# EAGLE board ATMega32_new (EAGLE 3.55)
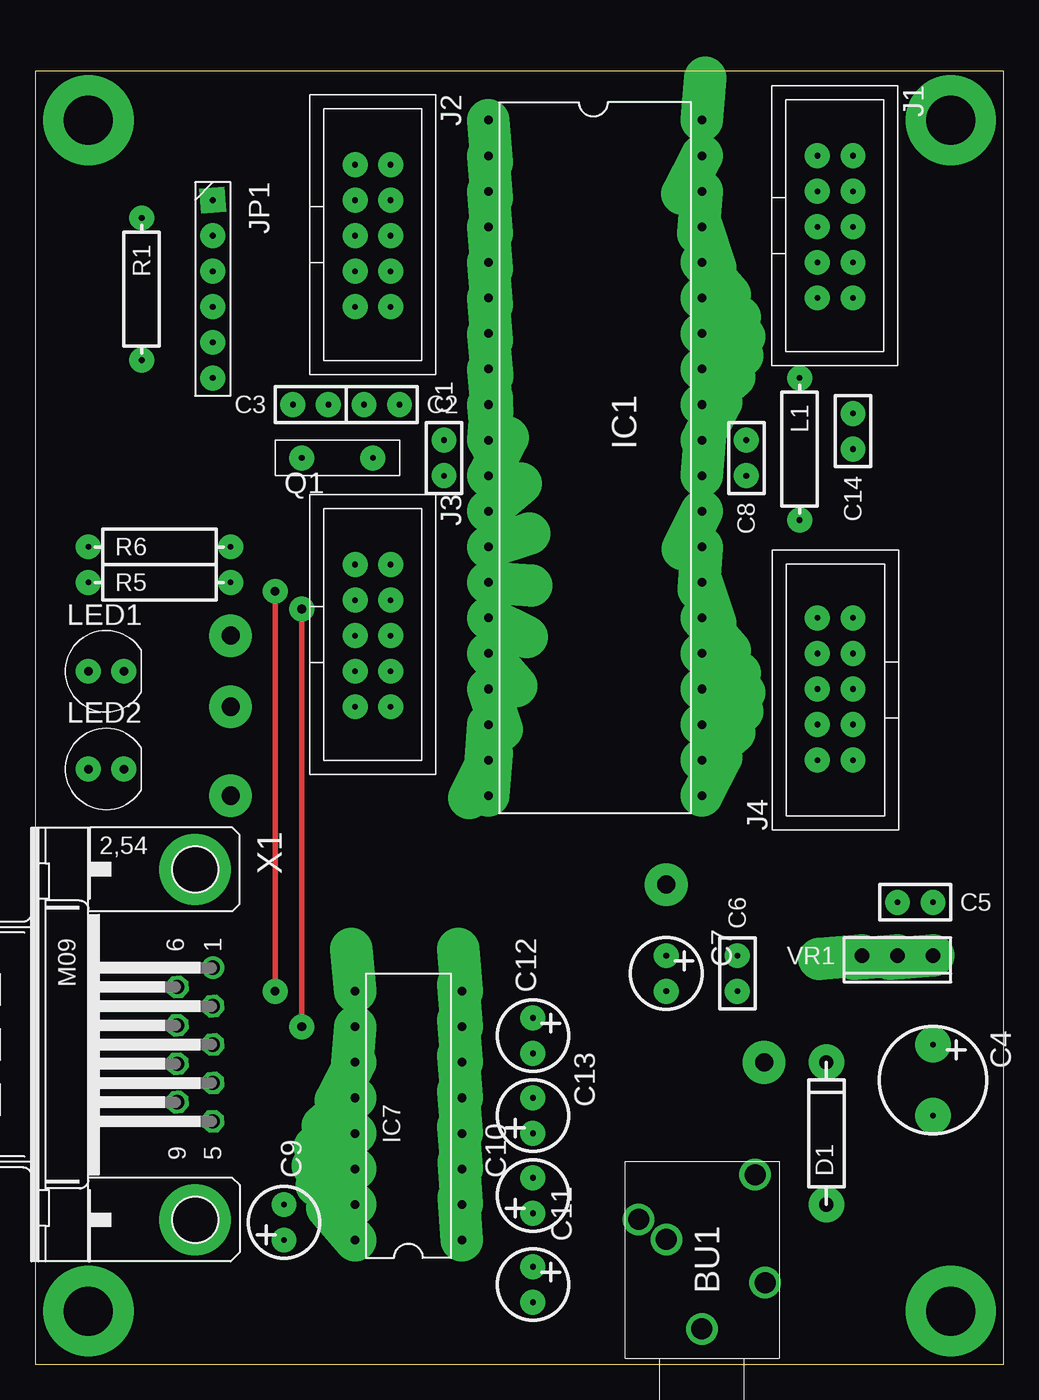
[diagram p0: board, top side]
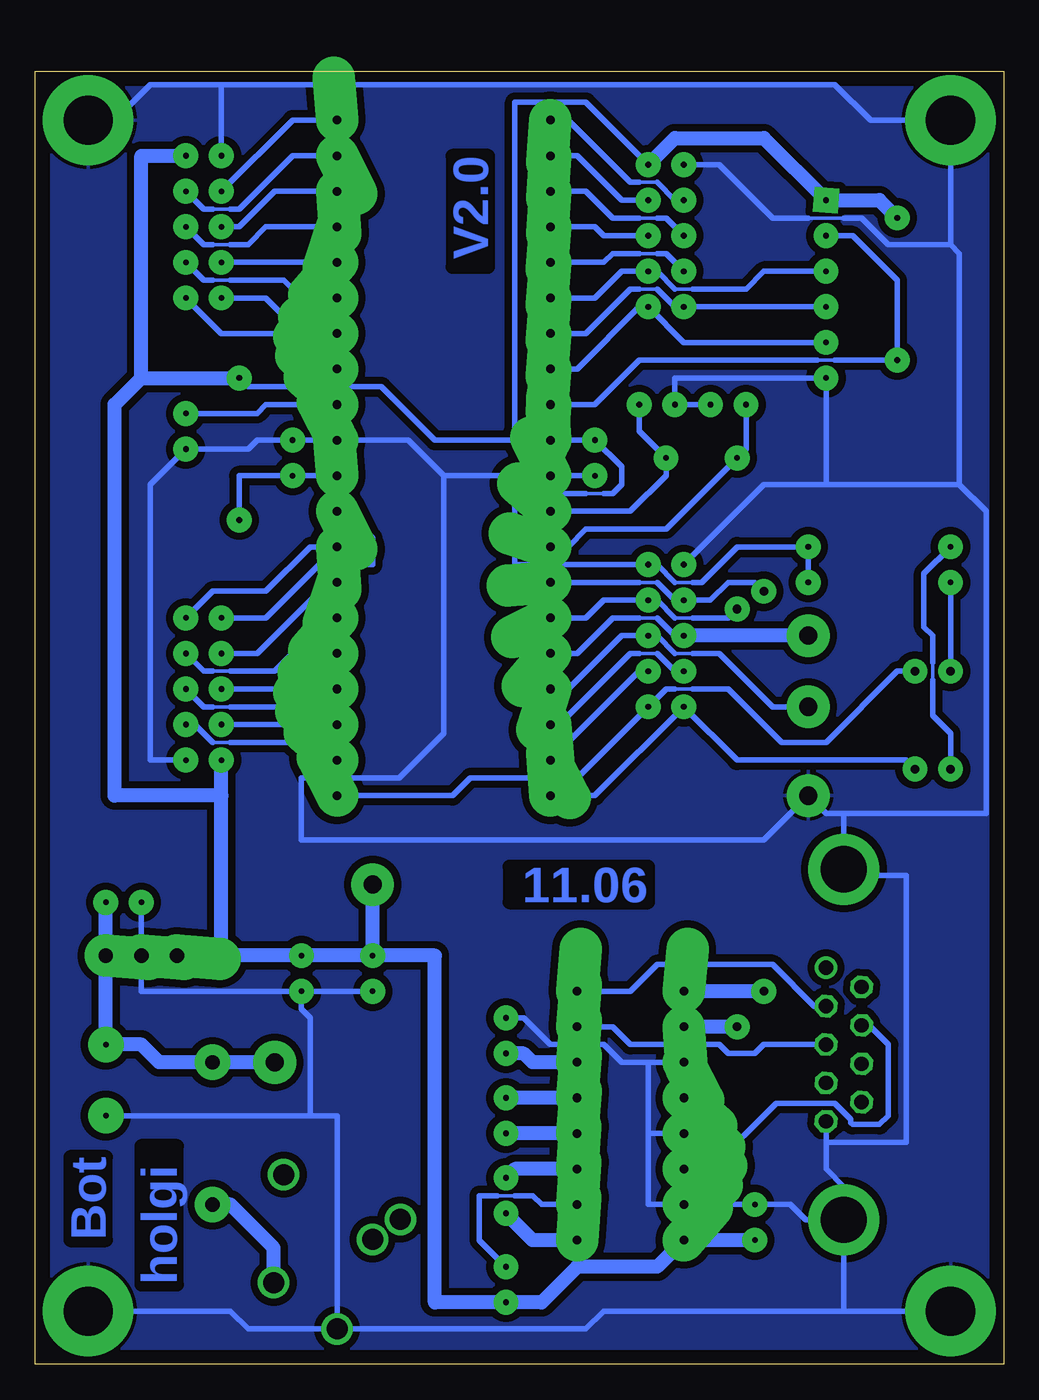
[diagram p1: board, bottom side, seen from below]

Size 69.19 x 92.38 mm. Coordinates in mm from the lower left corner, seen from the top.
Outline: 0,0 69.19,0 69.19,92.38 0,92.38 0,0
Copper layers used: Top, Bottom

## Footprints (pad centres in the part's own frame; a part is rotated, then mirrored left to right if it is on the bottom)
_3,5MM = drill 1.499 pad 2.184 round:  0,0;  3.302,-4.521;  7.823,4.521;  6.401,2.54;  11.024,-3.81
RM2,5 = drill 0.406 pad 1.778 round:  -1.27,0;  1.27,0
KO02 = drill 0.406 pad 2.54 round:  -2.54,0;  2.54,0
KO01 = drill 0.406 pad 1.778 round:  -1.27,0;  1.27,0
O_1A = drill 1.016 pad 2.54 round:  -5.08,0;  5.08,0
L-40B = drill 0.61 pad 3.048 offset:  -24.13,-7.62;  -21.59,-7.62;  -8.89,-7.62;  -6.35,-7.62;  -19.05,-7.62;  -16.51,-7.62;  -11.43,-7.62;  -13.97,-7.62;  -3.81,-7.62;  -1.27,-7.62;  1.27,-7.62;  3.81,-7.62;  6.35,-7.62;  8.89,-7.62;  11.43,-7.62;  13.97,-7.62;  16.51,-7.62;  19.05,-7.62;  21.59,-7.62;  24.13,-7.62;  24.13,7.62;  21.59,7.62;  19.05,7.62;  16.51,7.62;  13.97,7.62;  11.43,7.62;  8.89,7.62;  6.35,7.62;  3.81,7.62;  1.27,7.62;  -1.27,7.62;  -3.81,7.62;  -6.35,7.62;  -8.89,7.62;  -11.43,7.62;  -13.97,7.62;  -16.51,7.62;  -19.05,7.62;  -21.59,7.62;  -24.13,7.62
L-16B = drill 0.61 pad 3.048 offset:  -8.89,-3.81;  -6.35,-3.81;  6.35,-3.81;  8.89,-3.81;  -3.81,-3.81;  -1.27,-3.81;  3.81,-3.81;  1.27,-3.81;  8.89,3.81;  6.35,3.81;  3.81,3.81;  1.27,3.81;  -1.27,3.81;  -3.81,3.81;  -6.35,3.81;  -8.89,3.81
5 = drill 0.406 pad 1.778 round:  0,0;  2.54,0;  5.08,0;  7.62,0;  10.16,0;  10.16,2.54;  7.62,2.54;  5.08,2.54;  2.54,2.54;  0,2.54
6 = drill 0.406 pad 1.778 square:  0,0 | drill 0.406 pad 1.778 round:  5.08,0;  10.16,0;  12.7,0;  7.62,0;  2.54,0
S04 = drill 0.406 pad 1.778 round:  -5.08,0;  5.08,0
D_5MM = drill 0.61 pad 1.778 round:  -1.27,0;  1.27,0
GEL = drill 1.295 pad 3.048 round:  0,0
ARZ_ST = drill 0.406 pad 1.778 round:  -2.54,0;  2.54,0
HRUNG = drill 3.505 pad 6.452 round:  0,0
220A = drill 1.016 pad 3.048 offset:  -2.54,0;  0,0;  2.54,0
9HP = drill 1.016 pad 1.6 octagon:  5.486,1.27;  2.743,1.27;  0,1.27;  -2.743,1.27;  4.115,-1.27;  1.372,-1.27;  -1.372,-1.27;  -4.115,-1.27 | drill 1.016 pad 1.6 round:  -5.486,1.27 | drill 3.302 pad 5.08 round:  -12.522,0;  12.522,0

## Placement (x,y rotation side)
BU1  BU_3,5MM  [_3,5MM]  47.62,2.54 90 top
C1  C100NK  [RM2,5]  29.21,64.77 90 top
C2  22p  [RM2,5]  24.77,68.58 0 top
C3  22p  [RM2,5]  19.68,68.58 180 top
C4  470u/25  [KO02]  64.14,20.32 270 top
C5  C100NK  [RM2,5]  62.87,33.02 0 top
C6  C100NK  [RM2,5]  50.16,27.94 90 top
C7  100u  [KO01]  45.09,27.94 270 top
C8  C100NK  [RM2,5]  50.8,64.77 270 top
C9  10u  [KO01]  17.78,10.16 90 top
C10  10u  [KO01]  35.56,12.06 90 top
C11  10u  [KO01]  35.56,5.71 270 top
C12  10u  [KO01]  35.56,23.5 270 top
C13  10u  [KO01]  35.56,17.78 90 top
C14  C100NK  [RM2,5]  58.42,66.67 270 top
D1  1N4001  [O_1A]  56.52,16.51 90 top
IC1  90S8535-P  [L-40B]  40.01,64.77 270 top
IC7  MAX232  [L-16B]  26.67,17.78 90 top
J1  8BITPORT  [5]  55.88,86.36 270 top
J2  8BITPORT  [5]  22.86,85.72 270 top
J3  8BITPORT  [5]  22.86,57.15 270 top
J4  8BITPORT  [5]  58.42,43.18 90 top
JP1  PINHD-1X6  [6]  12.7,83.19 270 top
L1  100uH  [S04]  54.61,65.41 270 top
LED1  rot  [D_5MM]  5.08,49.53 0 top
LED2  grn  [D_5MM]  5.08,42.55 0 top
N1  Int1  [GEL]  13.97,46.99 0 top
N2  Int0  [GEL]  13.97,52.07 0 top
N3  gnd  [GEL]  13.97,40.64 0 top
N4  +5V  [GEL]  45.09,34.29 0 top
N5  +Ub  [GEL]  52.07,21.59 0 top
Q1  8MHz  [ARZ_ST]  21.59,64.77 0 top
R1  100k  [S04]  7.62,76.83 270 top
R5  1k  [S04]  8.89,55.88 0 top
R6  1k  [S04]  8.89,58.42 0 top
U$30  BOHRUNG  [HRUNG]  3.81,88.9 0 top
U$31  BOHRUNG  [HRUNG]  65.41,88.9 0 top
U$32  BOHRUNG  [HRUNG]  65.41,3.81 0 top
U$33  BOHRUNG  [HRUNG]  3.81,3.81 0 top
VR1  7805  [220A]  61.59,29.21 180 top
X1  M09HP  [9HP]  11.43,22.86 270 top

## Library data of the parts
BU1 = bts
C1-C14 D1 IC1 IC7 J1-J4 JP1 L1 LED1 LED2 Q1 R1 R5 R6 VR1 = holg_plt
N1-N5 U$30-U$33 = holgnorm
X1 = subd-a

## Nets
+5V: C1. C6. C7. C9. C11. IC1. IC7. J1. J2. J3. J4. JP1. L1. N4. R1. R5. R6. VR1.
GND: BU1. C1. C2. C3. C4. C5. C6. C7. C8. C9. C12. C14. IC1. IC7. J1. J2. J3. J4. JP1. N3. U$30. U$31. U$32. U$33. VR1. X1.
INT0: IC1. J3. N2.
INT1: IC1. J3. N1.
LCD_CS: IC1. J3.
LCD_RS: IC1. J3.
MISO: IC1. J2. JP1.
MOSI: IC1. J2. JP1.
N$1: IC1. J4.
N$2: IC1. J4.
N$3: IC1. J4.
N$4: IC1. J4.
N$5: IC1. J4.
N$6: C3. IC1. Q1.
N$7: IC1. J4.
N$8: C2. IC1. Q1.
N$9: C12. IC7.
N$10: C11. IC7.
N$11: IC1. J4.
N$12: C10. IC7.
N$13: C13. IC7.
N$14: IC1. J1.
N$15: C10. IC7.
N$16: IC1. J4.
N$17: C13. IC7.
N$18: IC1. J1.
N$19: IC1. J1.
N$21: IC1. J1.
N$22: IC1. J1.
N$23: IC1. J1.
N$24: C8. IC1. L1.
N$25: IC1. J1.
N$26: IC1. J1.
N$27: C14. IC1.
N$29: IC1. J3. LED1.
N$30: IC1. J2.
N$31: IC1. J2.
N$32: IC1. J2.
N$33: IC1. J2.
N$34: IC1. J2.
N$35: IC1. J3. LED2.
N$36: LED1. R5.
N$37: LED2. R6.
N$42: C4. C5. D1. N5. VR1.
N$50: BU1. D1.
RESET: IC1. JP1. R1.
RTS_OUT: IC7. X1.
RXD: IC1. IC7. J3.
RXD_IN: IC7. X1.
SCK: IC1. J2. JP1.
TXD: IC1. IC7. J3.
TXD_OUT: IC7. X1.

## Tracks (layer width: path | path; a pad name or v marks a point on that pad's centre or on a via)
+5V
  Bottom 0.254: 23.5,55.88 22.23,55.88 | 28.57,62.23 29.84,62.23
  Bottom 0.406: 34.92,66.04 32.38,66.04 C1. 27.3,64.14 27.3,62.87 27.94,62.23 28.57,62.23 | 54.61,70.48 53.98,69.85 44.45,69.85 40.64,66.04 34.92,66.04 | R5. R6. 19.05,58.42 21.59,55.88 22.23,55.88 | 23.5,55.88 24.77,57.15 J3. 34.92,57.15 34.92,62.23 29.84,62.23 | J2. 29.84,90.17 34.92,90.17 34.92,66.04
  Bottom 1.016: 17.78,8.89 IC7. 24.77,6.99 30.48,6.99 33.02,4.45 C11. 40.64,4.45 40.64,29.21 45.09,29.21 | 55.88,29.21 C6. 45.09,29.21 | 55.88,29.21 VR1. | 7.62,81.92 8.89,83.19 12.7,83.19 17.14,87.63 23.5,87.63 J2. | 55.88,40.64 63.5,40.64 63.5,68.58 61.59,70.48 | 45.09,29.21 N4. | J1. 61.59,86.36 61.59,70.48 | 61.59,70.48 54.61,70.48 | 55.88,40.64 J4. | 55.88,29.21 55.88,40.64
GND
  Bottom 0.254: 11.43,81.92 13.97,81.92
  Bottom 0.406: X1. 11.43,12.7 12.7,13.97 12.7,15.88 | 12.7,15.88 12.7,17.37 | 12.7,15.88 6.99,15.88 6.99,34.92 8.89,34.92 9.35,35.38 11.43,35.38 11.43,39.37 | X1. 14.15,10.34 15.24,11.43 C9. 22.86,11.43 25.4,11.43 25.4,16.51 | 25.4,16.51 22.86,16.51 | 25.4,16.51 25.4,21.59 | 25.4,21.59 22.86,21.59 | 25.4,21.59 27.3,21.59 28.57,22.86 32.38,22.86 34.29,24.77 35.56,24.77 | 11.43,3.81 X1. | U$33. 11.43,3.81 | 47.62,2.54 29.84,2.54 28.57,3.81 11.43,3.81 | 61.59,33.02 61.59,29.21 61.59,26.67 50.16,26.67 | 50.16,26.67 C7. | U$32. 55.24,3.81 53.98,2.54 47.62,2.54 | 49.53,17.78 47.62,17.78 47.62,2.54 | 49.53,17.78 C4. | 49.53,17.78 49.53,24.77 50.16,25.4 50.16,26.67 | 22.86,85.72 20.32,85.72 16.51,81.92 13.97,81.92 | 3.17,62.87 1.27,60.96 1.27,39.37 11.43,39.37 | 55.88,91.44 12.06,91.44 9.53,88.9 U$30. 3.81,80.01 | 55.88,91.44 60.96,91.44 63.5,88.9 U$31. | 11.43,81.92 10.16,81.92 8.26,80.01 3.81,80.01 | 40.01,63.5 32.38,63.5 29.21,63.5 | 55.88,91.44 55.88,86.36 | 11.43,39.37 12.7,39.37 N3. 17.14,37.47 50.16,37.47 50.16,41.91 43.18,41.91 40.01,45.09 40.01,63.5 | 3.81,80.01 3.17,79.38 3.17,62.87 | 3.17,62.87 12.7,62.87 | 20.95,68.58 23.5,68.58 23.5,70.48 12.7,70.48 12.7,62.87 | 22.86,57.15 17.14,62.87 12.7,62.87 | 58.42,43.18 60.96,43.18 60.96,62.87 C14. 53.98,65.41 53.34,66.04 50.8,66.04 47.62,66.04 42.55,66.04 40.01,63.5
  pour Bottom (isolate 0.508): 0.64,91.44 0.64,0.64 68.58,0.64 68.58,91.44
INT0
  Bottom 0.254: 24.77,53.34 26.04,53.34
  Bottom 0.406: 22.86,52.07 23.5,52.07 24.77,53.34 | 32.38,50.8 30.48,50.8 27.94,53.34 26.04,53.34
  Bottom 1.016: N2. 22.86,52.07
INT1
  Bottom 0.254: 22.23,50.8 23.5,50.8
  Bottom 0.406: 23.5,50.8 24.77,52.07 25.4,52.07 27.3,52.07 31.11,48.26 32.38,48.26 | N1. 16.51,46.99 20.32,50.8 22.23,50.8
LCD_CS
  Bottom 0.254: 24.77,50.8 26.04,50.8
  Bottom 0.406: 22.86,49.53 23.5,49.53 24.77,50.8 | 32.38,45.72 31.75,45.72 26.67,50.8 26.04,50.8
LCD_RS
  Bottom 0.406: 25.4,49.53 26.04,49.53 32.38,43.18
MISO
  Bottom 0.254: 24.77,76.83 26.04,76.83
  Bottom 0.406: 12.7,75.56 22.86,75.56 23.5,75.56 24.77,76.83 | 32.38,73.66 29.84,73.66 26.67,76.83 26.04,76.83
MOSI
  Bottom 0.254: 22.23,76.83 23.5,76.83
  Bottom 0.406: 23.5,76.83 24.77,78.11 25.4,78.11 27.3,78.11 29.21,76.2 32.38,76.2 | 12.7,78.11 17.14,78.11 18.41,76.83 22.23,76.83
N$1
  Bottom 0.254: 55.24,44.45 56.52,44.45
  Bottom 0.406: 47.62,43.18 49.53,43.18 50.8,44.45 55.24,44.45 | 56.52,44.45 57.78,45.72 58.42,45.72
N$2
  Bottom 0.406: 47.62,45.72 55.88,45.72
N$3
  Bottom 0.254: 55.24,46.99 56.52,46.99
  Bottom 0.406: 47.62,48.26 48.9,48.26 50.16,46.99 55.24,46.99 | 56.52,46.99 57.15,46.99 58.42,48.26
N$4
  Bottom 0.406: 47.62,50.8 48.9,50.8 51.44,48.26 55.88,48.26
N$5
  Bottom 0.254: 55.24,49.53 56.52,49.53
  Bottom 0.406: 47.62,53.34 48.26,53.34 52.07,49.53 55.24,49.53 | 56.52,49.53 57.15,49.53 58.42,50.8
N$6
  Bottom 0.406: 32.38,58.42 31.11,58.42 29.84,59.69 24.13,59.69 19.05,64.77 18.41,65.41 C3.
N$7
  Bottom 0.406: 47.62,55.88 48.26,55.88 53.34,50.8 55.88,50.8
N$8
  Bottom 0.406: C2. 26.04,66.67 Q1. 24.13,63.5 26.67,60.96 32.38,60.96
N$9
  Bottom 1.016: 30.48,21.59 33.66,21.59 34.29,22.23 C12.
N$10
  Bottom 0.254: 34.92,12.06 36.2,12.06
  Bottom 0.406: 30.48,11.43 33.02,11.43 33.66,12.06 34.92,12.06 | 36.2,12.06 37.47,12.06 37.47,8.89 35.56,6.99
N$11
  Bottom 0.406: 47.62,58.42 49.53,58.42 52.7,55.24 56.52,55.24 58.42,53.34
N$12
  Bottom 1.016: 30.48,13.97 34.92,13.97 C10.
N$13
  Bottom 1.016: 30.48,19.05 C13.
N$14
  Bottom 0.406: IC1. 50.8,88.9 55.88,83.82
N$15
  Bottom 1.016: 35.56,10.79 33.66,8.89 30.48,8.89
N$16
  Bottom 0.406: 47.62,60.96 46.99,60.96 45.09,59.05 45.09,57.15 48.9,57.15 52.7,53.34 55.88,53.34
N$17
  Bottom 1.016: 30.48,16.51 35.56,16.51
N$18
  Bottom 0.254: 55.24,82.55 56.52,82.55
  Bottom 0.406: 47.62,86.36 50.8,86.36 54.61,82.55 55.24,82.55 | 58.42,83.82 57.15,82.55 56.52,82.55
N$19
  Bottom 0.406: 47.62,83.82 52.07,83.82 54.61,81.28 55.88,81.28
N$21
  Bottom 0.254: 55.24,80.01 56.52,80.01
  Bottom 0.406: 47.62,81.28 52.7,81.28 53.98,80.01 55.24,80.01 | 58.42,81.28 57.15,80.01 56.52,80.01
N$22
  Bottom 0.406: 47.62,78.74 55.88,78.74
N$23
  Bottom 0.254: 55.24,77.47 56.52,77.47
  Bottom 0.406: 47.62,76.2 50.16,76.2 51.44,77.47 55.24,77.47 | 58.42,78.74 57.15,77.47 56.52,77.47
N$24
  Bottom 0.406: 47.62,63.5 C8. 54.61,63.5 L1.
N$25
  Bottom 0.406: 47.62,73.66 50.16,73.66 52.7,76.2 55.88,76.2
N$26
  Bottom 0.406: 47.62,71.12 49.53,71.12 52.07,73.66 55.88,73.66 58.42,76.2
N$27
  Bottom 0.406: 47.62,68.58 52.7,68.58 53.34,67.94 58.42,67.94
N$29
  Bottom 0.254: 22.23,48.26 23.5,48.26
  Bottom 0.406: 23.5,48.26 24.13,48.26 25.4,46.99 30.48,41.91 38.1,41.91 39.37,40.64 47.62,40.64 | LED1. 7.62,49.53 12.7,44.45 15.88,44.45 19.68,48.26 22.23,48.26
N$30
  Bottom 0.254: 24.77,79.38 26.04,79.38
  Bottom 0.406: 22.86,78.11 24.13,79.38 24.77,79.38 | 32.38,78.74 28.57,78.74 27.94,79.38 26.04,79.38
N$31
  Bottom 0.406: 25.4,80.64 28.57,80.64 29.21,81.28 32.38,81.28
N$32
  Bottom 0.254: 24.77,81.92 26.04,81.92
  Bottom 0.406: 22.86,80.64 24.13,81.92 24.77,81.92 | 32.38,83.82 29.84,83.82 27.94,81.92 26.04,81.92
N$33
  Bottom 0.406: 25.4,83.19 27.3,83.19 30.48,86.36 32.38,86.36
N$34
  Bottom 0.254: 24.77,84.45 26.04,84.45
  Bottom 0.406: 22.86,83.19 23.5,83.19 24.77,84.45 | 32.38,88.9 31.11,88.9 26.67,84.45 26.04,84.45
N$35
  Bottom 0.406: LED2. 6.99,43.18 19.05,43.18 22.86,46.99 29.21,40.64 32.38,40.64
N$36
  Bottom 0.406: 3.81,49.53 3.81,55.88
N$37
  Bottom 0.254: 5.08,48.9 5.08,50.16
  Bottom 0.406: 3.81,58.42 5.71,56.52 5.71,52.7 5.08,52.07 5.08,50.16 | 3.81,42.55 3.81,45.09 5.08,46.35 5.08,48.9
N$42
  Bottom 1.016: C5. 64.14,29.21 64.14,22.86 61.59,22.86 60.33,21.59 D1. N5.
N$50
  Bottom 1.016: 52.15,5.84 52.15,8.33 55.24,11.43 56.52,11.43
RESET
  Bottom 0.254: 12.06,71.75 13.34,71.75
  Bottom 0.406: JP1. 10.79,80.64 7.62,77.47 R1. 12.06,71.75 | 32.38,68.58 29.21,68.58 26.04,71.75 13.34,71.75
RTS_OUT
  Bottom 0.406: 10.16,24.23 9.63,24.23 8.26,22.86 8.26,17.78 8.89,17.14 10.79,17.14 10.92,17.27 10.92,17.53 12.06,18.67 16.26,18.67 20.95,13.97 22.86,13.97
RXD  (via drill 0.61 pad 1.78)
  Top 0.406: v17.14,26.67 v17.14,55.24
  Bottom 0.254: 24.77,55.88 26.04,55.88
  Bottom 0.406: v17.14,55.24 17.78,55.88 19.68,55.88 20.95,54.61 22.86,54.61 23.5,54.61 24.77,55.88 | 26.04,55.88 32.38,55.88
  Bottom 1.016: v17.14,26.67 22.86,26.67
RXD_IN
  Bottom 0.406: 12.7,25.6 13.54,25.6 16.51,28.57 24.77,28.57 26.67,26.67 30.48,26.67
SCK
  Bottom 0.406: 12.7,73.03 22.86,73.03 25.4,75.56 26.04,75.56 30.48,71.12 32.38,71.12
TXD  (via drill 0.61 pad 1.78)
  Top 0.406: v19.05,24.13 v19.05,53.98
  Bottom 0.254: 22.23,53.34 23.5,53.34
  Bottom 0.406: 23.5,53.34 24.77,54.61 25.4,54.61 28.57,54.61 29.84,53.34 32.38,53.34 | v19.05,53.98 19.68,53.34 22.23,53.34
  Bottom 1.016: v19.05,24.13 22.86,24.13
TXD_OUT
  Bottom 0.406: 30.48,24.13 27.94,24.13 26.67,22.86 20.32,22.86 19.68,22.23 17.78,22.23 17.14,22.86 12.7,22.86

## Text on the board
Bottom: V2.0 | 11.06 | Bot | holgi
